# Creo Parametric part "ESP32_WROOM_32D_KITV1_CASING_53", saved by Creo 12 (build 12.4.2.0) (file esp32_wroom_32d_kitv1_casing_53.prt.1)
Units: Custom; MM, KILOGRAM, SECS

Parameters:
  PTC_WM_ITERATION = "0"
  PTC_WM_VERSION = "-.0"
  PTC_WM_LIFECYCLE_STATE = "In Work"
  PTC_WM_LIFECYCLE = "MO_CADDocument"
  PTC_WM_CREATED_BY = "Maximilian Roepper (Z0017RMS: MO)"
  PTC_WM_CREATED_ON = "18-Sep-26 11:36:42 AM"
  PTC_WM_MODIFIED_BY = "Maximilian Roepper (Z0017RMS: MO)"
  PTC_WM_MODIFIED_ON = "18-Sep-26 11:36:46 AM"
  PDMLINKNUMBER = "PDM000071455153"
  PTC_WM_NAME = "esp32_wroom_32d_kitv1_casing_53.prt"
  PTC_WM_NUMBER = "PDM000071455153"

Other parameters: WEIGHT, WEIGHT_FACTOR, WEIGHT_ADD, _MASS_TEMP, _DIFF_TEMP, MC_ERRORS, SUPPLIER

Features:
  1. coordinate system
  2. datum plane "PRT_YZ"
  3. datum plane "PRT_XY"
  4. datum plane "PRT_XZ"
  5. coordinate system
  6. datum axis
  7. datum axis
  8. datum axis
  9. coordinate system
  10. imported feature
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
Other named items: PRT, SIEMENS_MO, DRW_VIEW_ORG, PRT_X, PRT_Y, PRT_Z, CS0, ROUGH_GROB

Layers: 00_STD_CSYS-KSYS, 01_STD_PLANES-EBENEN, 02_STD_AXES-ACHSEN, 03_STD_CSYS-KSYS, 24_IMPORT_FEAT-IMPORT_KE

Surfaces: 5 plane, 1 cylinder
